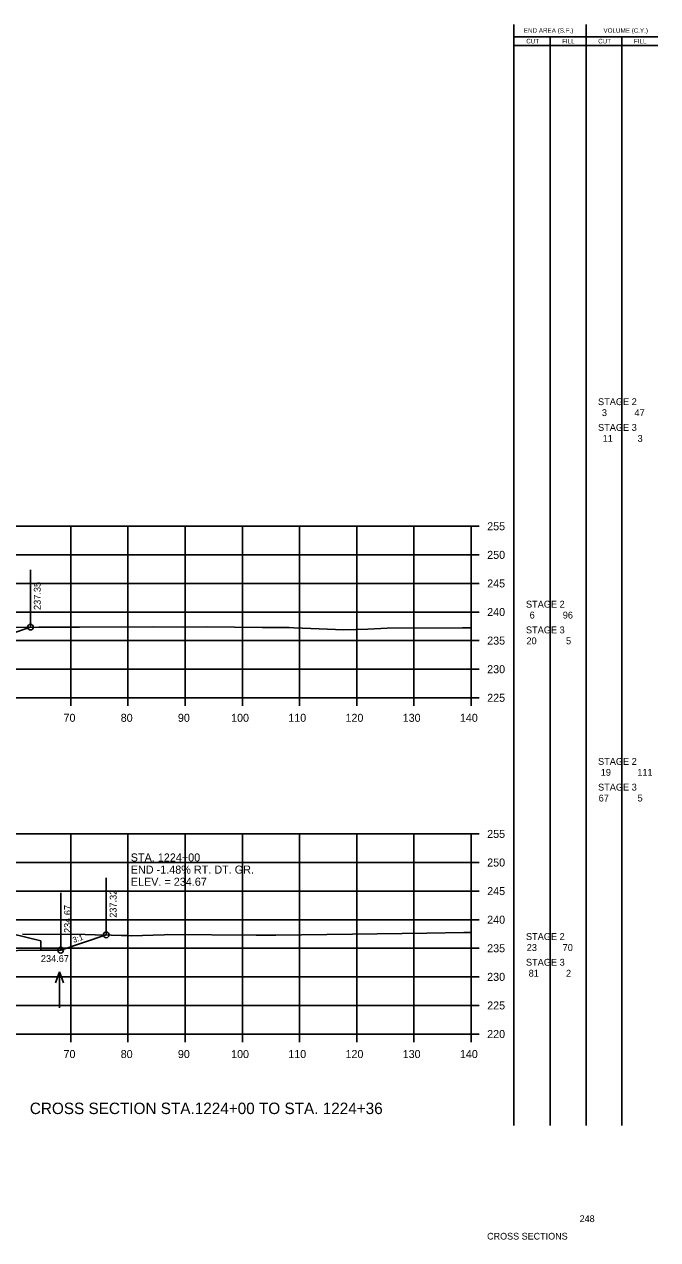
# Model space of a CAD drawing. Extents: x 1342547 to 1344156, y -1532351 to -1517216.
# Drawn here: x 1342764.7 to 1342875.5, y -1531300.4 to -1531087.9 of the extents above; entities that cross this region are included whole.
import ezdxf

# ---------------------------------------------------------------- set-up
doc = ezdxf.new("R2010")
doc.units = 0
for name, color, linetype in [('Level 2', 7, 'Continuous'), ('R_Axis', 7, 'Continuous'), ('R_Axis Annot', 7, 'Continuous'), ('R_Border Notes', 7, 'Continuous'), ('R_Draft', 7, 'Continuous'), ('R_Exist Surface', 7, 'Continuous'), ('R_Fin Surface', 7, 'Continuous'), ('R_Grid', 7, 'Continuous'), ('R_No Plot', 7, 'Continuous'), ('R_Water', 7, 'Continuous'), ('R_Water Annot', 7, 'Continuous'), ('R_Xsect Elev', 7, 'Continuous'), ('R_Xsect Slope', 7, 'Continuous')]:
    doc.layers.add(name, color=color, linetype=linetype)

msp = doc.modelspace()

# ---------------------------------------------------------------- linework, layer by layer
at = {"layer": 'Level 2'}
for p, q in [((1342850.33, -1531280.46), (1342850.32, -1531087.86)), ((1342862.99, -1531280.46), (1342862.99, -1531087.86)), ((1342850.32, -1531090.02), (1342863.59, -1531090.02)), ((1342856.66, -1531280.46), (1342856.66, -1531090.02)), ((1342863.59, -1531090.02), (1342875.48, -1531090.02)), ((1342869.23, -1531280.46), (1342869.23, -1531090.02)), ((1342850.32, -1531091.58), (1342863.59, -1531091.58)), ((1342863.59, -1531091.58), (1342875.48, -1531091.58))]:
    msp.add_line(p, q, dxfattribs=at)
at = {"layer": 'R_Axis'}
for p, q in [((1342842.87, -1531205.65), (1342842.87, -1531175.65)), ((1342844.27, -1531175.65), (1342842.87, -1531175.65)), ((1342844.27, -1531180.65), (1342842.87, -1531180.65)), ((1342844.27, -1531185.65), (1342842.87, -1531185.65)), ((1342844.27, -1531190.65), (1342842.87, -1531190.65)), ((1342844.27, -1531195.65), (1342842.87, -1531195.65)), ((1342844.27, -1531200.65), (1342842.87, -1531200.65)), ((1342562.87, -1531205.65), (1342842.87, -1531205.65)), ((1342772.87, -1531207.05), (1342772.87, -1531205.65)), ((1342782.87, -1531207.05), (1342782.87, -1531205.65)), ((1342792.87, -1531207.05), (1342792.87, -1531205.65)), ((1342802.87, -1531207.05), (1342802.87, -1531205.65)), ((1342812.87, -1531207.05), (1342812.87, -1531205.65)), ((1342822.87, -1531207.05), (1342822.87, -1531205.65)), ((1342832.87, -1531207.05), (1342832.87, -1531205.65)), ((1342842.87, -1531207.05), (1342842.87, -1531205.65)), ((1342844.27, -1531205.65), (1342842.87, -1531205.65)), ((1342842.87, -1531264.46), (1342842.87, -1531229.46)), ((1342844.27, -1531229.46), (1342842.87, -1531229.46)), ((1342844.27, -1531234.46), (1342842.87, -1531234.46)), ((1342844.27, -1531239.46), (1342842.87, -1531239.46)), ((1342844.27, -1531244.46), (1342842.87, -1531244.46)), ((1342844.27, -1531249.46), (1342842.87, -1531249.46)), ((1342844.27, -1531254.46), (1342842.87, -1531254.46)), ((1342844.27, -1531259.46), (1342842.87, -1531259.46)), ((1342562.87, -1531264.46), (1342842.87, -1531264.46)), ((1342772.87, -1531265.86), (1342772.87, -1531264.46)), ((1342782.87, -1531265.86), (1342782.87, -1531264.46)), ((1342792.87, -1531265.86), (1342792.87, -1531264.46)), ((1342802.87, -1531265.86), (1342802.87, -1531264.46)), ((1342812.87, -1531265.86), (1342812.87, -1531264.46)), ((1342822.87, -1531265.86), (1342822.87, -1531264.46)), ((1342832.87, -1531265.86), (1342832.87, -1531264.46)), ((1342842.87, -1531265.86), (1342842.87, -1531264.46)), ((1342844.27, -1531264.46), (1342842.87, -1531264.46))]:
    msp.add_line(p, q, dxfattribs=at)
at = {"layer": 'R_Exist Surface'}
for points in [[(1342755.62, -1531193.33), (1342767.31, -1531193.28), (1342774.38, -1531193.28), (1342787.28, -1531193.22), (1342792.42, -1531193.28), (1342796.6, -1531193.24), (1342806.39, -1531193.34), (1342811.02, -1531193.36), (1342811.87, -1531193.41), (1342816.28, -1531193.56), (1342820.59, -1531193.78), (1342824.81, -1531193.63), (1342828.16, -1531193.47), (1342841.36, -1531193.42), (1342842.87, -1531193.4)], [(1342764.44, -1531246.98), (1342775.4, -1531247.08), (1342777.15, -1531247.09), (1342779.92, -1531247.15), (1342781.73, -1531247.25), (1342782.94, -1531247.24), (1342783.51, -1531247.28), (1342789.21, -1531247.1), (1342789.72, -1531247.08), (1342805.29, -1531247.16), (1342808.74, -1531247.14), (1342822.1, -1531247.01), (1342835.09, -1531246.81), (1342841.59, -1531246.73), (1342842.87, -1531246.71)]]:
    msp.add_lwpolyline(points, dxfattribs=at)
at = {"layer": 'R_Fin Surface'}
for points in [[(1342762.37, -1531194.44), (1342765.81, -1531193.29)], [(1342771.1, -1531249.79), (1342779.07, -1531247.13)]]:
    msp.add_lwpolyline(points, dxfattribs=at)
at = {"layer": 'R_Grid'}
for p, q in [((1342562.87, -1531175.65), (1342842.87, -1531175.65)), ((1342772.87, -1531205.65), (1342772.87, -1531175.65)), ((1342782.87, -1531205.65), (1342782.87, -1531175.65)), ((1342792.87, -1531205.65), (1342792.87, -1531175.65)), ((1342802.87, -1531205.65), (1342802.87, -1531175.65)), ((1342812.87, -1531205.65), (1342812.87, -1531175.65)), ((1342822.87, -1531205.65), (1342822.87, -1531175.65)), ((1342832.87, -1531205.65), (1342832.87, -1531175.65)), ((1342842.87, -1531205.65), (1342842.87, -1531175.65)), ((1342562.87, -1531180.65), (1342842.87, -1531180.65)), ((1342562.87, -1531185.65), (1342842.87, -1531185.65)), ((1342562.87, -1531190.65), (1342842.87, -1531190.65)), ((1342562.87, -1531195.65), (1342842.87, -1531195.65)), ((1342562.87, -1531200.65), (1342842.87, -1531200.65)), ((1342562.87, -1531205.65), (1342842.87, -1531205.65)), ((1342562.87, -1531229.46), (1342842.87, -1531229.46)), ((1342772.87, -1531264.46), (1342772.87, -1531229.46)), ((1342782.87, -1531264.46), (1342782.87, -1531229.46)), ((1342792.87, -1531264.46), (1342792.87, -1531229.46)), ((1342802.87, -1531264.46), (1342802.87, -1531229.46)), ((1342812.87, -1531264.46), (1342812.87, -1531229.46)), ((1342822.87, -1531264.46), (1342822.87, -1531229.46)), ((1342832.87, -1531264.46), (1342832.87, -1531229.46)), ((1342842.87, -1531264.46), (1342842.87, -1531229.46)), ((1342562.87, -1531234.46), (1342842.87, -1531234.46)), ((1342562.87, -1531239.46), (1342842.87, -1531239.46)), ((1342562.87, -1531244.46), (1342842.87, -1531244.46)), ((1342562.87, -1531249.46), (1342842.87, -1531249.46)), ((1342562.87, -1531254.46), (1342842.87, -1531254.46)), ((1342562.87, -1531259.46), (1342842.87, -1531259.46)), ((1342562.87, -1531264.46), (1342842.87, -1531264.46))]:
    msp.add_line(p, q, dxfattribs=at)
at = {"layer": 'R_No Plot'}
for centre in [(1342765.81, -1531193.29), (1342765.81, -1531193.29), (1342779.07, -1531247.13), (1342779.07, -1531247.13), (1342771.1, -1531249.79), (1342771.1, -1531249.79)]:
    msp.add_circle(centre, 0.5, dxfattribs=at)
at = {"layer": 'R_Water'}
for p, q in [((1342767.64, -1531249.82), (1342771.1, -1531249.79)), ((1342770.89, -1531253.58), (1342770.19, -1531255.5)), ((1342770.89, -1531259.86), (1342770.89, -1531253.58)), ((1342770.89, -1531253.58), (1342771.59, -1531255.5))]:
    msp.add_line(p, q, dxfattribs=at)
msp.add_lwpolyline([(1342759.47, -1531246.91), (1342759.5, -1531249.91), (1342767.64, -1531249.82), (1342767.63, -1531248.16), (1342762.37, -1531246.88)], close=True, dxfattribs=at)
at = {"layer": 'R_Xsect Elev'}
for p, q in [((1342765.81, -1531193.29), (1342765.81, -1531183.29)), ((1342779.07, -1531247.13), (1342779.07, -1531237.13)), ((1342771.1, -1531249.79), (1342771.1, -1531239.79))]:
    msp.add_line(p, q, dxfattribs=at)

# ---------------------------------------------------------------- texts
at = {"layer": 'Level 2'}
for s, height, p in [('END AREA (S.F.)', 0.7937, (1342852.08, -1531089.33)), ('CUT', 0.794, (1342852.5, -1531091.19)), ('FILL', 0.794, (1342858.76, -1531091.19)), ('CUT', 0.794, (1342865.07, -1531091.19)), ('VOLUME (C.Y.)', 0.7937, (1342865.99, -1531089.33)), ('FILL', 0.794, (1342871.33, -1531091.19)), (' STAGE 2 ', 1.2, (1342864.6, -1531154.46)), ('3', 1.2, (1342865.72, -1531156.38)), ('47', 1.2, (1342871.43, -1531156.38)), (' STAGE 3 ', 1.2, (1342864.6, -1531158.96)), ('11', 1.2, (1342865.86, -1531160.88)), ('3', 1.2, (1342871.96, -1531160.88)), (' STAGE 2 ', 1.2, (1342852, -1531189.88)), ('6', 1.2, (1342853.09, -1531191.79)), ('96', 1.2, (1342858.88, -1531191.79)), (' STAGE 3 ', 1.2, (1342852, -1531194.38)), ('20', 1.2, (1342852.53, -1531196.29)), ('5', 1.2, (1342859.45, -1531196.29)), (' STAGE 2 ', 1.2, (1342864.6, -1531217.38)), ('19', 1.2, (1342865.52, -1531219.29)), ('111', 1.2, (1342871.91, -1531219.29)), (' STAGE 3 ', 1.2, (1342864.6, -1531221.88)), ('67', 1.2, (1342865.16, -1531223.79)), ('5', 1.2, (1342871.96, -1531223.79)), (' STAGE 2 ', 1.2, (1342852, -1531248.01)), ('23', 1.2, (1342852.58, -1531249.93)), ('70', 1.2, (1342858.86, -1531249.93)), (' STAGE 3 ', 1.2, (1342852, -1531252.51)), ('81', 1.2, (1342852.92, -1531254.43)), ('2', 1.2, (1342859.45, -1531254.43))]:
    msp.add_text(s, height=height, dxfattribs=at).set_placement(p)
at = {"layer": 'R_Axis Annot'}
for s, p in [('255', (1342845.67, -1531176.35)), ('250', (1342845.67, -1531181.35)), ('245', (1342845.67, -1531186.35)), ('240', (1342845.67, -1531191.35)), ('235', (1342845.67, -1531196.35)), ('230', (1342845.67, -1531201.35)), ('225', (1342845.67, -1531206.35)), ('70', (1342771.6, -1531209.85)), ('80', (1342781.6, -1531209.85)), ('90', (1342791.6, -1531209.85)), ('100', (1342800.9, -1531209.85)), ('110', (1342810.9, -1531209.85)), ('120', (1342820.9, -1531209.85)), ('130', (1342830.9, -1531209.85)), ('140', (1342840.9, -1531209.85)), ('255', (1342845.67, -1531230.16)), ('250', (1342845.67, -1531235.16)), ('245', (1342845.67, -1531240.16)), ('240', (1342845.67, -1531245.16)), ('235', (1342845.67, -1531250.16)), ('230', (1342845.67, -1531255.16)), ('225', (1342845.67, -1531260.16)), ('220', (1342845.67, -1531265.16)), ('70', (1342771.6, -1531268.66)), ('80', (1342781.6, -1531268.66)), ('90', (1342791.6, -1531268.66)), ('100', (1342800.9, -1531268.66)), ('110', (1342810.9, -1531268.66)), ('120', (1342820.9, -1531268.66)), ('130', (1342830.9, -1531268.66)), ('140', (1342840.9, -1531268.66))]:
    msp.add_text(s, height=1.4, dxfattribs=at).set_placement(p)
at = {"layer": 'R_Border Notes'}
for s, height, p in [('248', 1.178, (1342861.83, -1531297.35)), ('CROSS SECTIONS', 1.1775, (1342845.65, -1531300.41))]:
    msp.add_text(s, height=height, dxfattribs=at).set_placement(p)
at = {"layer": 'R_Draft'}
msp.add_text('CROSS SECTION STA.1224+00 TO STA. 1224+36', height=2, dxfattribs=at).set_placement((1342765.71, -1531278.46))
at = {"layer": 'R_Water Annot'}
for s, p in [('STA. 1224+00', (1342783.35, -1531234.29)), ('STA. 1224+00', (1342783.35, -1531234.29)), ('END -1.48% RT. DT. GR.', (1342783.35, -1531236.41)), ('END -1.48% RT. DT. GR.', (1342783.35, -1531236.41)), ('ELEV. = 234.67', (1342783.35, -1531238.53)), ('ELEV. = 234.67', (1342783.35, -1531238.53))]:
    msp.add_text(s, height=1.4147, dxfattribs=at).set_placement(p)
at = {"layer": 'R_Xsect Elev'}
for s, p in [('237.35', (1342767.61, -1531190.29)), ('237.32', (1342780.87, -1531244.13)), ('234.67', (1342772.9, -1531246.79))]:
    msp.add_text(s, height=1.2, rotation=90, dxfattribs=at).set_placement(p)
msp.add_text('234.67', height=1.2, dxfattribs=at).set_placement((1342767.64, -1531251.86))
at = {"layer": 'R_Xsect Slope'}
msp.add_text('3:1', height=1, rotation=18.4349, dxfattribs=at).set_placement((1342773.39, -1531248.53))

doc.saveas('drawing.dxf')
